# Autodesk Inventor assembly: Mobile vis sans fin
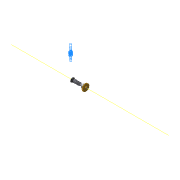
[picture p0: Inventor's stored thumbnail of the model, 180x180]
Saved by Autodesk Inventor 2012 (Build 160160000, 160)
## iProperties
Created: 2011-07
Part Number: Mobile vis sans fin
Document SubType Name: Assembly
Designer: Laur
Author: Laur
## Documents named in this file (6)
- D:\Formulaire\Sujet CIM 4 Poissy\Modélisation_7970_shimano\Mobile vis sans fin.iam
- D:\Formulaire\Sujet CIM 4 Poissy\Modélisation_7970_shimano\pièces mobile vis sans fin\vis sans fin arbrée.iam
- D:\Formulaire\Sujet CIM 4 Poissy\Modélisation_7970_shimano\éléments standards\PARTserver35515621\WA673SSA.iam
- D:\Formulaire\Sujet CIM 4 Poissy\Modélisation_7970_shimano\éléments standards\PARTserver35516212\RA144ZZA.iam
- D:\Formulaire\Sujet CIM 4 Poissy\Modélisation_7970_shimano\Roue droite 43 dents module 0,3.ipt
- D:\Formulaire\Sujet CIM 4 Poissy\Modélisation_7970_shimano\Roue codeuse.ipt
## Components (5 placed, 5 different names)
1. vis sans fin arbrée:1 [sub-assembly] — coaxialité  rlt 673 / arbre, pos. axiale rlt 673 / arbre, coaxialité rlt 144 / arbre, pos. axiale rlt 144 / arbre, Placage:5, Placage:6, Placage:7, Angle:1
2. WA673SSA:1 [sub-assembly] — coaxialité  rlt 673 / arbre, pos. axiale rlt 673 / arbre
3. RA144ZZA:1 [sub-assembly] — coaxialité rlt 144 / arbre, pos. axiale rlt 144 / arbre
4. Roue droite 43 dents module 0,3:1 — Placage:5, Placage:6
5. Roue codeuse:1 — Affleurement:1, Angle:1
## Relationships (9: Mate 7, Flush 1, Angle 1)
- coaxialité  rlt 673 / arbre [Mate]: vis sans fin arbrée:1 ↔ WA673SSA:1
- pos. axiale rlt 673 / arbre [Mate]: vis sans fin arbrée:1 ↔ WA673SSA:1
- coaxialité rlt 144 / arbre [Mate]: vis sans fin arbrée:1 ↔ RA144ZZA:1
- pos. axiale rlt 144 / arbre [Mate]: vis sans fin arbrée:1 ↔ RA144ZZA:1
- Placage:5 [Mate]: vis sans fin arbrée:1 ↔ Roue droite 43 dents module 0,3:1
- Placage:6 [Mate]: vis sans fin arbrée:1 ↔ Roue droite 43 dents module 0,3:1
- Affleurement:1 [Flush]: Roue codeuse:1
- Placage:7 [Mate]: vis sans fin arbrée:1
- Angle:1: vis sans fin arbrée:1 ↔ Roue codeuse:1
